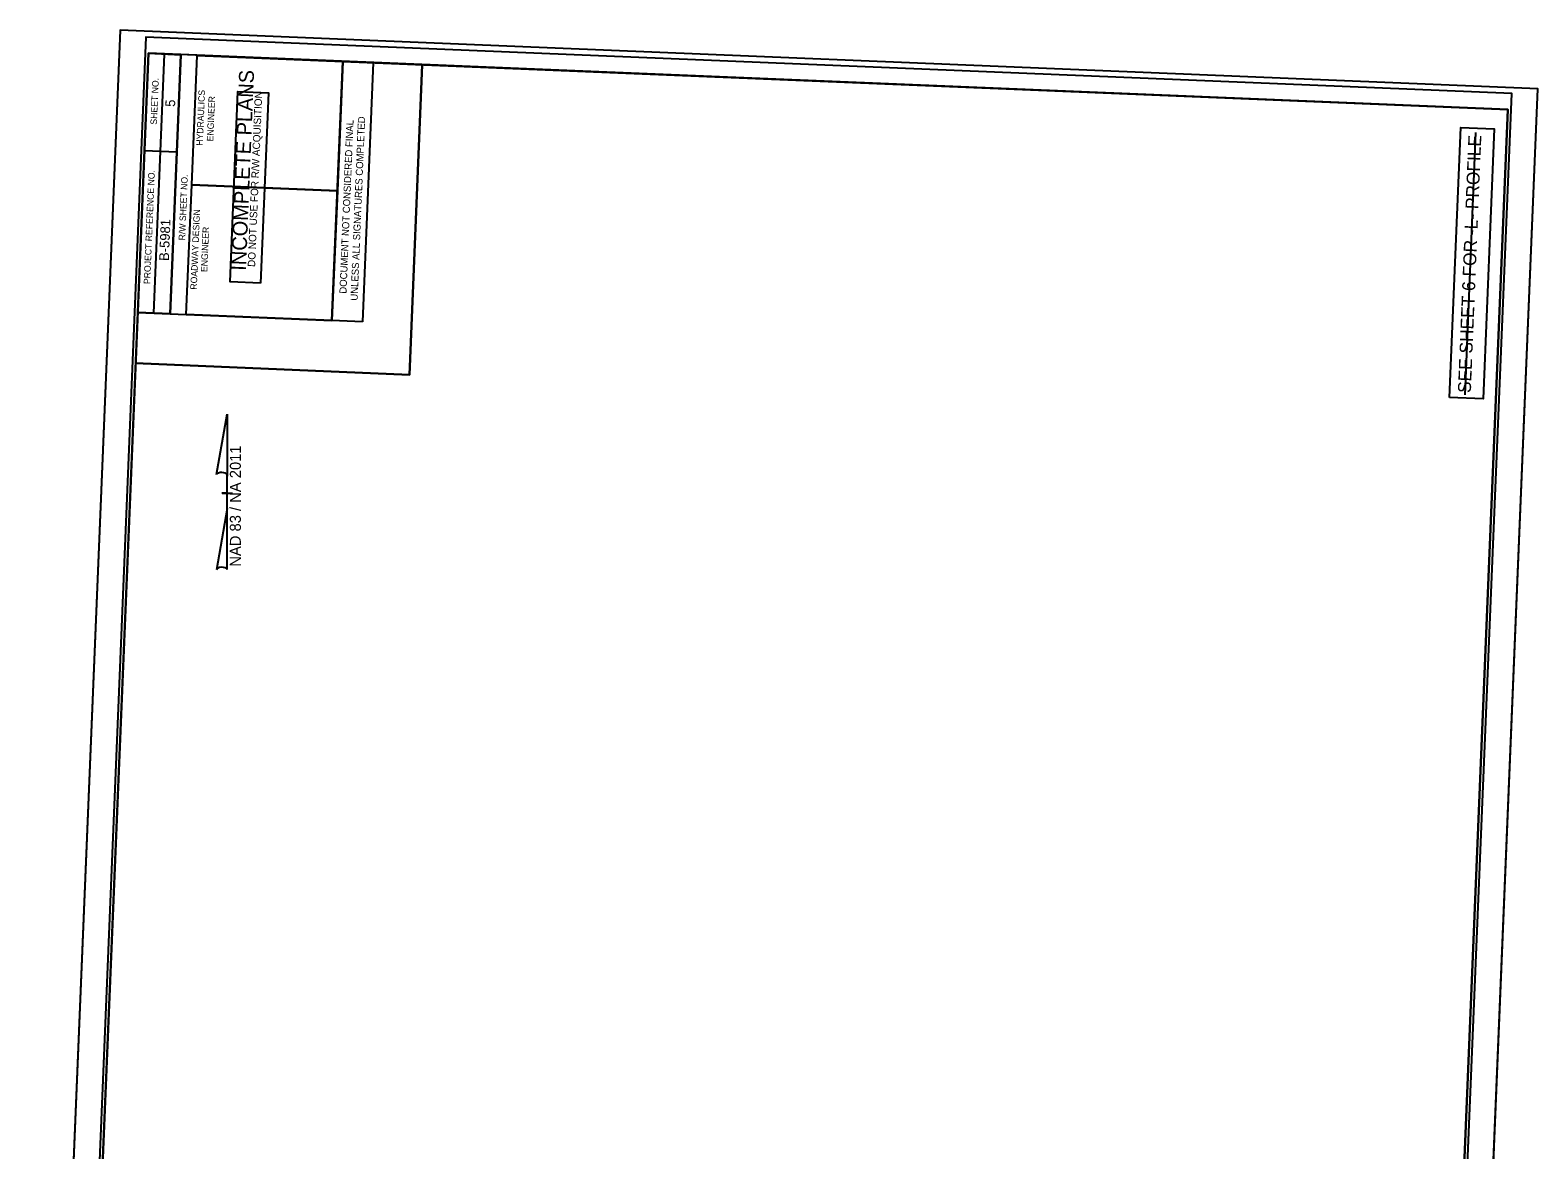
# Model space of a CAD drawing. Extents: x 2265722 to 2266885, y 510440 to 512168.
# Drawn here: x 2265722 to 2266885, y 511304 to 512168 of the extents above; entities that cross this region are included whole.
import ezdxf

# ---------------------------------------------------------------- set-up
doc = ezdxf.new("R2010")
doc.units = 0
for name, color, linetype in [('Prop DSN Text', 7, 'Continuous'), ('Prop North Arrow NAD83 for Plan Sheets CELL', 7, 'Continuous'), ('Sheet Clip Boundary CELL', 7, 'Continuous'), ('Sheet Cutting Line CELL', 7, 'Continuous'), ('Sheet Data Field CELL', 7, 'Continuous'), ('Sheet Layout Plan Border', 7, 'Continuous'), ('Sheet North Arrow Point CELL', 7, 'Continuous'), ('Sheet Plan CELL', 7, 'Continuous'), ('Sheet Plan Layout CELL', 7, 'Continuous'), ('Sheet Plot Border Inside CELL', 7, 'Continuous'), ('Sheet Plot Border Outside CELL', 7, 'Continuous'), ('Sheet Sticker Exception Certification CELL', 7, 'Continuous'), ('Sheet Sticker Incomplete CELL', 7, 'Continuous')]:
    doc.layers.add(name, color=color, linetype=linetype)

msp = doc.modelspace()

# ---------------------------------------------------------------- linework, layer by layer
at = {"layer": 'Prop DSN Text'}
msp.add_line((2266829.2, 511886.3), (2266837.5, 512088.6), dxfattribs=at)
msp.add_lwpolyline([(2266817.2, 511884.2), (2266825.9, 512092.5), (2266851.7, 512091.5), (2266843.1, 511883.1)], close=True, dxfattribs=at)
at = {"layer": 'Prop North Arrow NAD83 for Plan Sheets CELL'}
for p, q in [((2265865.6, 511824.9), (2265873.9, 511871.3)), ((2265873.9, 511871.3), (2265873.9, 511871.3)), ((2265873.9, 511871.3), (2265873.9, 511871.3)), ((2265873.9, 511871.3), (2265873.9, 511823.5)), ((2265873.9, 511798.7), (2265873.9, 511824.9)), ((2265873.9, 511823.5), (2265873.9, 511824.8)), ((2265869.9, 511810.3), (2265869.8, 511810.3)), ((2265869.9, 511810.3), (2265877.9, 511810.3)), ((2265873.4, 511810.3), (2265869.9, 511810.3)), ((2265873.9, 511798.7), (2265865.5, 511751.4)), ((2265873.9, 511751.6), (2265873.9, 511798.7))]:
    msp.add_line(p, q, dxfattribs=at)
for centre, start_param, end_param in [((2265869.8, 511824.4), 0.216388, 2.908219), ((2265869.8, 511751.3), 0.201328, 3.141593)]:
    msp.add_ellipse(centre, major_axis=(4.23, -0.03), ratio=0.461098, start_param=start_param, end_param=end_param, dxfattribs=at)
at = {"layer": 'Sheet Clip Boundary CELL'}
msp.add_lwpolyline([(2265950.3, 510683.5), (2266061.7, 510678.9), (2266649.9, 510654.6), (2266801.9, 510648.3), (2266862.2, 512106.3), (2266024.4, 512140.9), (2266014.5, 511901.8), (2265803.2, 511910.6), (2265752.9, 510691.7)], close=True, dxfattribs=at)
at = {"layer": 'Sheet Cutting Line CELL'}
for p, q in [((2265791.3, 512167.5), (2265721.8, 510485.5)), ((2266815.9, 510440.3), (2266885.4, 512122.3))]:
    msp.add_line(p, q, dxfattribs=at)
at = {"layer": 'Sheet Layout Plan Border'}
msp.add_lwpolyline([(2266801.9, 510648.3), (2266862.2, 512106.3), (2266024.4, 512140.9), (2266014.5, 511901.8), (2265803.2, 511910.6), (2265752.9, 510691.7)], close=True, dxfattribs=at)
at = {"layer": 'Sheet North Arrow Point CELL'}
msp.add_line((2265880.9, 512024), (2265880.9, 512024), dxfattribs=at)
at = {"layer": 'Sheet Plan CELL'}
for p, q in [((2265817.3, 511949.2), (2265825.6, 512149.1)), ((2265829.9, 511948.7), (2265838.1, 512148.6)), ((2265829.9, 511948.7), (2265838.1, 512148.6)), ((2265810, 512074.7), (2265835, 512073.7)), ((2265846.5, 512048.2), (2265958.8, 512043.5)), ((2265829.9, 511948.7), (2265842.3, 511948.2))]:
    msp.add_line(p, q, dxfattribs=at)
for points in [[(2265813.1, 512149.7), (2265751.1, 510650.9), (2266800.3, 510607.5), (2266862.2, 512106.3)], [(2266800.3, 510607.5), (2265751.2, 510650.9), (2265804.8, 511949.7), (2265954.7, 511943.6), (2265963, 512143.4), (2266862.2, 512106.3)], [(2265804.8, 511949.7), (2265813.1, 512149.7), (2265838.1, 512148.6), (2265829.9, 511948.7)], [(2265846.5, 512048.2), (2265850.6, 512148.1), (2265963, 512143.4), (2265958.9, 512043.5)], [(2265842.3, 511948.2), (2265846.5, 512048.2), (2265958.9, 512043.5), (2265954.7, 511943.6)]]:
    msp.add_lwpolyline(points, close=True, dxfattribs=at)
at = {"layer": 'Sheet Plan Layout CELL'}
for points in [[(2266014.5, 511901.8), (2266024.4, 512140.9), (2265813.1, 512149.7), (2265803.2, 511910.6)], [(2265751.2, 510650.9), (2266800.3, 510607.5), (2266862.2, 512106.3), (2266024.4, 512140.9), (2266014.5, 511901.8), (2265803.2, 511910.6)]]:
    msp.add_lwpolyline(points, close=True, dxfattribs=at)
at = {"layer": 'Sheet Plot Border Inside CELL'}
msp.add_lwpolyline([(2266796.4, 510454.1), (2266865.2, 512118.7), (2265811.1, 512162.2), (2265742.3, 510497.6)], close=True, dxfattribs=at)
at = {"layer": 'Sheet Plot Border Outside CELL'}
msp.add_lwpolyline([(2266815.9, 510440.3), (2266885.4, 512122.3), (2265791.3, 512167.5), (2265721.8, 510485.5)], close=True, dxfattribs=at)
at = {"layer": 'Sheet Sticker Exception Certification CELL'}
for p, q in [((2265954.7, 511943.6), (2265963, 512143.4)), ((2265963, 512143.4), (2265986.5, 512142.5)), ((2265986.5, 512142.5), (2265978.2, 511942.6)), ((2265978.2, 511942.6), (2265954.7, 511943.6))]:
    msp.add_line(p, q, dxfattribs=at)
at = {"layer": 'Sheet Sticker Incomplete CELL'}
msp.add_lwpolyline([(2265899.6, 511972.4), (2265876.2, 511973.4), (2265882.2, 512120.2), (2265905.7, 512119.3)], close=True, dxfattribs=at)

# ---------------------------------------------------------------- texts
at = {"layer": 'Prop DSN Text'}
msp.add_text('SEE SHEET 6 FOR -L- PROFILE', height=10, rotation=87.6342, dxfattribs=at).set_placement((2266833.6, 511887.5))
at = {"layer": 'Prop North Arrow NAD83 for Plan Sheets CELL'}
msp.add_text('NAD 83 / NA 2011', height=8.5, rotation=89.9761, dxfattribs=at).set_placement((2265884.4, 511753.7))
at = {"layer": 'Sheet Data Field CELL'}
for s, p in [('5', (2265833.6, 512108.3)), ('B-5981   ', (2265828.8, 511989.4))]:
    msp.add_text(s, height=7.5, rotation=87.6342, dxfattribs=at).set_placement(p)
at = {"layer": 'Sheet Plan CELL'}
for s, p in [('SHEET NO.', (2265819.6, 512094.6)), ('HYDRAULICS', (2265855, 512078.3)), ('ENGINEER', (2265863.1, 512081.7)), ('PROJECT REFERENCE NO.', (2265814.4, 511971.6)), ('R/W SHEET NO.', (2265841.4, 512005.3)), ('ROADWAY DESIGN', (2265850.4, 511967.3)), ('ENGINEER', (2265858.5, 511980.9))]:
    msp.add_text(s, height=5, rotation=87.6342, dxfattribs=at).set_placement(p)
at = {"layer": 'Sheet Sticker Exception Certification CELL'}
for s, p in [('DOCUMENT NOT CONSIDERED FINAL', (2265965.9, 511964.2)), ('UNLESS ALL SIGNATURES COMPLETED', (2265974.5, 511958.8))]:
    msp.add_text(s, height=5.5, rotation=87.6342, dxfattribs=at).set_placement(p)
at = {"layer": 'Sheet Sticker Incomplete CELL'}
for s, height, p in [('INCOMPLETE PLANS', 11.52, (2265888.3, 511981.8)), ('DO NOT USE FOR R/W ACQUISITION', 5.76, (2265895.4, 511984.8))]:
    msp.add_text(s, height=height, rotation=87.6342, dxfattribs=at).set_placement(p)

doc.saveas('drawing.dxf')
